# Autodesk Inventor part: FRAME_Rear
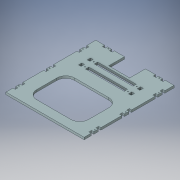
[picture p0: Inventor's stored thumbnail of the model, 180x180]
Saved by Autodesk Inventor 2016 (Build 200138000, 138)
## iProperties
Created: 2016-01
Part Number: FRAME_Rear
Material: Generic
Document SubType Name: Modeling
Designer: John
Density: 1 g/cm^3
Appearance: Default
Author: John
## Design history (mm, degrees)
feature "SOLID1"
body "Solid1"
